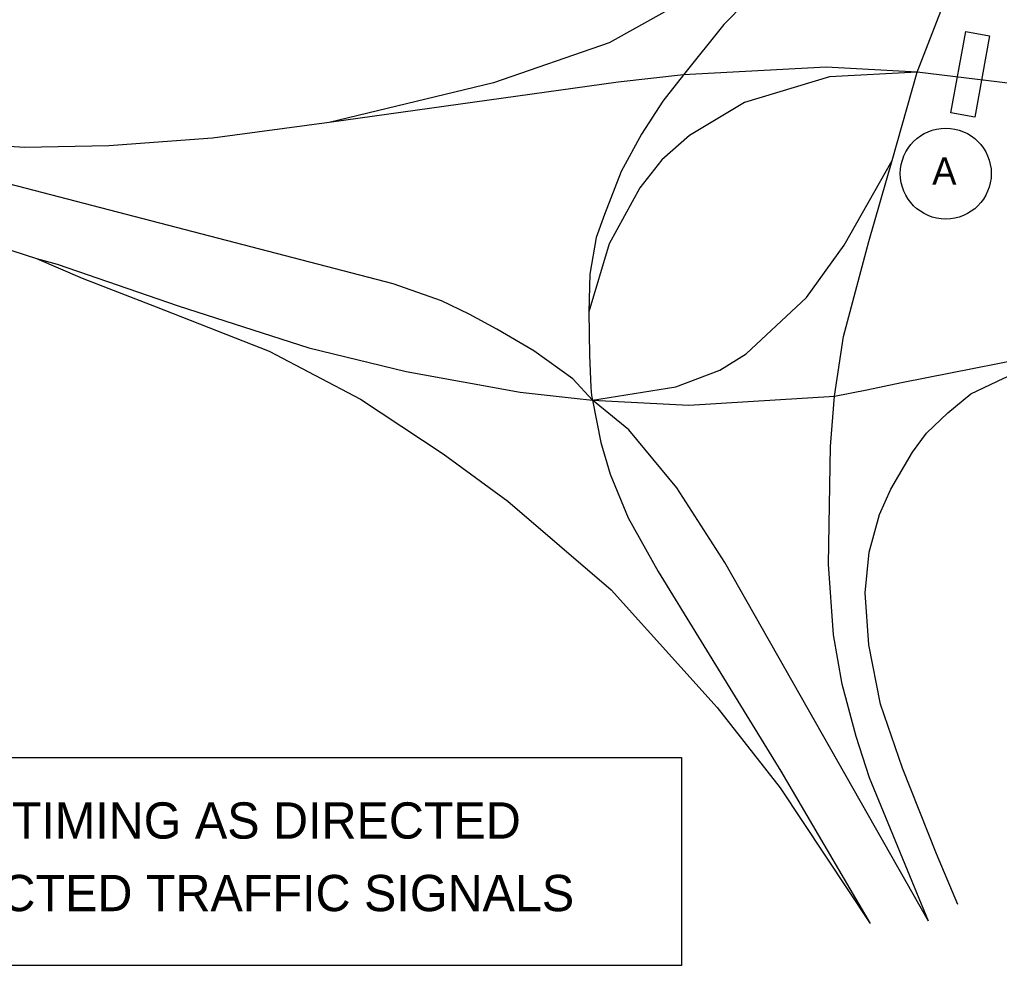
# Model space of a CAD drawing. Extents: x 886234 to 968767, y 455416 to 684046.
# Drawn here: x 907843 to 911897, y 510281 to 514192 of the extents above; entities that cross this region are included whole.
import ezdxf

# ---------------------------------------------------------------- set-up
doc = ezdxf.new("R2010")
doc.units = 0
doc.layers.add('TC LABEL TEXT', color=7, linetype='Continuous')

msp = doc.modelspace()

# ---------------------------------------------------------------- linework, layer by layer
at = {"layer": 'TC LABEL TEXT'}
for points in [[(911557.3, 513975.4), (911683.2, 514303), (911778.9, 514534.8), (911874.4, 514718.1), (911975.3, 514872.5), (912116.4, 515028.7), (912474, 515305.9)], [(911365.9, 514751.5), (911023.4, 514534.8), (910852.1, 514413.9), (910283, 514096.4), (909804.5, 513930.1), (909123.7, 513766.3)], [(911365.9, 514751.5), (911028.4, 514449.2), (910756.4, 514172), (910589.5, 513963.3)], [(911557.3, 513975.4), (911194.6, 513955.3), (910842.1, 513849.4), (910615.4, 513713.4), (910499.6, 513612.6), (910408.9, 513496.7), (910282.3, 513264.4), (910198.1, 512984.3)], [(911557.3, 513975.4), (911179.5, 513995.6), (910589.5, 513963.3)], [(911453.4, 513609.3), (911557.3, 513975.4)], [(912375.3, 513868.7), (912045.1, 513915.9), (911557.3, 513975.4)], [(910589.5, 513963.3), (910319.5, 513933.5), (909123.7, 513766.3)], [(910589.5, 513963.3), (910504.6, 513854.5), (910416.1, 513717.9), (910331.9, 513564.2), (910262.8, 513385.8), (910229.1, 513290.4), (910202.4, 513138.8), (910198.1, 512984.3)], [(909123.7, 513766.3), (908640.9, 513701.2), (908212.9, 513670.4), (907863.7, 513663.6), (907332.7, 513697.5)], [(910213.2, 512618), (910132, 512707), (909971, 512822.1), (909817, 512912.3), (909703.8, 512974.3), (909588.8, 513029.2), (909389.1, 513099.5), (907282, 513646.8)], [(910213.2, 512618), (910558.3, 512673.5), (910739.8, 512742), (910849.3, 512810.5), (911098.9, 513043.1), (911255.1, 513259.8), (911453.4, 513609.3)], [(911214.2, 512635.1), (911251.9, 512881.4), (911357.1, 513274.7), (911453.4, 513609.3)], [(907127.6, 513464.9), (907281.4, 513408), (907913.3, 513204.3)], [(907913.3, 513204.3), (907998, 513181.4), (908498.8, 513007.9), (909039.8, 512835.2), (909442.3, 512737.4), (909914.1, 512651.4), (910137.1, 512627), (910213.2, 512618)], [(907913.3, 513204.3), (908101.8, 513122.9), (908408.5, 513004.4), (908875.7, 512820.3), (909253.8, 512622.1), (909596.2, 512396), (909863.3, 512200.7), (910291.2, 511834.2), (910729.5, 511347.7), (910989.7, 511015.4), (911362.2, 510454.7)], [(910198.1, 512984.3), (910201.1, 512804.1), (910207, 512670.3), (910209.6, 512637.1), (910213.2, 512618)], [(911214.2, 512635.1), (911348.9, 512661.7), (911492.1, 512691.6), (912191.7, 512829.2)], [(911725.4, 510533.2), (911636.2, 510741.9), (911496.3, 511096.6), (911405, 511361.9), (911356.8, 511606.1), (911341.4, 511821.5), (911358.4, 511989.1), (911400.8, 512146.2), (911448, 512250.3), (911537.1, 512403), (911594.9, 512481.3), (911683, 512566.6), (911779.1, 512644), (911915.1, 512709.6), (912191.7, 512829.2)], [(910213.2, 512618), (910612.4, 512597.3), (911214.2, 512635.1)], [(911603.8, 510464.3), (911359.5, 511056.5), (911304.7, 511227.8), (911246.5, 511443.6), (911210.6, 511647.8), (911190.3, 511939.9), (911198.3, 512426.5), (911214.2, 512635.1)], [(911603.8, 510464.3), (910760.3, 511947.2), (910561.7, 512255.5), (910363.1, 512495.3), (910213.2, 512618)], [(910213.2, 512618), (910247.7, 512443.7), (910287.1, 512312.3), (910361, 512131.6), (910484.8, 511910.4), (910993.1, 511083.9), (911362.2, 510454.7)]]:
    msp.add_lwpolyline(points, dxfattribs=at)
for points in [[(911695.6, 513806.2), (911757.4, 514143.1), (911856.4, 514125), (911794.6, 513788)], [(904885.7, 511140.2), (910581, 511140.2), (910581, 510281), (904885.7, 510281)]]:
    msp.add_lwpolyline(points, close=True, dxfattribs=at)
msp.add_circle((911675, 513555.3), 188.1, dxfattribs=at)

# ---------------------------------------------------------------- texts
for s, height, p in [('A', 112.5, (911618.9, 513509.8)), ('ADJUST EXISTING SIGNAL TIMING AS DIRECTED', 150, (905191.5, 510805.2)), ('BY THE ENGINEER AT IMPACTED TRAFFIC SIGNALS', 150, (905077.8, 510505.2))]:
    msp.add_text(s, height=height, dxfattribs=at).set_placement(p)

doc.saveas('drawing.dxf')
